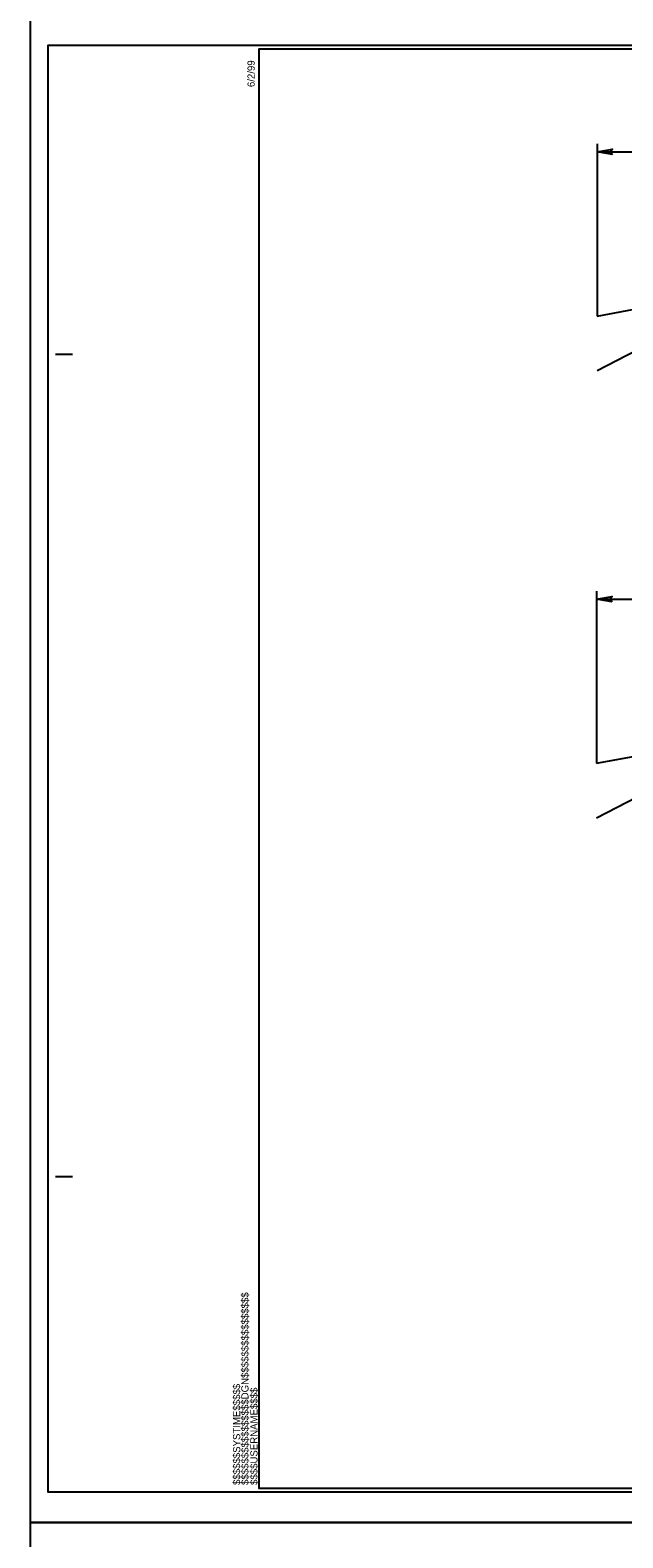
# Model space of a CAD drawing. Extents: x 981824 to 982276, y 44828 to 45204.
# Drawn here: x 982094.4 to 982129, y 45001.1 to 45089.1 of the extents above; entities that cross this region are included whole.
import ezdxf

# ---------------------------------------------------------------- set-up
doc = ezdxf.new("R2010")
doc.units = 0
for name, color, linetype in [('Old_Level_1', 7, 'Continuous'), ('Old_Level_18', 7, 'Continuous'), ('Old_Level_40', 7, 'Continuous'), ('Old_Level_41', 7, 'Continuous'), ('Old_Level_50', 7, 'Continuous'), ('Old_Level_51', 7, 'Continuous'), ('Old_Level_52', 7, 'Continuous'), ('Typical Terminator CELL', 7, 'Continuous')]:
    doc.layers.add(name, color=color, linetype=linetype)

msp = doc.modelspace()

# ---------------------------------------------------------------- linework, layer by layer
at = {"layer": 'Old_Level_1'}
for p, q in [((982127.455, 45082.429), (982127.455, 45072.384)), ((982127.455, 45081.961), (982136.994, 45081.961)), ((982127.455, 45069.205), (982136.994, 45074.163)), ((982127.455, 45072.384), (982136.994, 45074.163)), ((982127.423, 45056.322), (982127.423, 45046.278)), ((982127.423, 45055.854), (982136.961, 45055.854)), ((982127.423, 45043.098), (982136.961, 45048.056)), ((982127.423, 45046.278), (982136.961, 45048.056))]:
    msp.add_line(p, q, dxfattribs=at)
at = {"layer": 'Old_Level_18'}
msp.add_line((982107.72, 45003.969), (982107.72, 45003.969), dxfattribs=at)
msp.add_line((982107.72, 45003.969), (982107.72, 45003.969), dxfattribs=at)
msp.add_line((982107.72, 45003.969), (982107.72, 45003.969), dxfattribs=at)
msp.add_lwpolyline([(982227.72, 45087.969), (982107.72, 45087.969), (982107.72, 45003.969), (982227.72, 45003.969)], close=True, dxfattribs=at)
at = {"layer": 'Old_Level_40'}
msp.add_line((982107.72, 45003.969), (982107.72, 45003.969), dxfattribs=at)
msp.add_line((982107.72, 45003.969), (982107.72, 45003.969), dxfattribs=at)
msp.add_line((982107.72, 45003.969), (982107.72, 45003.969), dxfattribs=at)
msp.add_line((982107.72, 45003.969), (982107.72, 45003.969), dxfattribs=at)
msp.add_line((982107.72, 45003.969), (982107.72, 45003.969), dxfattribs=at)
msp.add_line((982107.72, 45003.969), (982107.72, 45003.969), dxfattribs=at)
at = {"layer": 'Old_Level_41'}
for p, q in [((982095.84, 45070.169), (982096.84, 45070.169)), ((982095.84, 45022.169), (982096.84, 45022.169))]:
    msp.add_line(p, q, dxfattribs=at)
msp.add_lwpolyline([(982110.72, 45003.969), (982110.72, 45003.969)], dxfattribs=at)
msp.add_lwpolyline([(982110.72, 45003.969), (982110.72, 45003.969)], dxfattribs=at)
at = {"layer": 'Old_Level_50'}
msp.add_line((982094.36, 45001.969), (982094.36, 45001.969), dxfattribs=at)
msp.add_lwpolyline([(982228.72, 45088.173), (982095.4, 45088.173), (982095.4, 45003.765), (982228.72, 45003.765)], close=True, dxfattribs=at)
at = {"layer": 'Old_Level_51'}
for points in [[(982229.08, 45089.969), (982094.36, 45089.969), (982094.36, 45001.969), (982229.08, 45001.969)], [(982229.08, 45001.969), (982094.36, 45001.969), (982094.36, 44913.969), (982229.08, 44913.969)]]:
    msp.add_lwpolyline(points, close=True, dxfattribs=at)
at = {"layer": 'Old_Level_52'}
msp.add_line((982095.4, 45003.765), (982095.4, 45003.765), dxfattribs=at)
at = {"layer": 'Typical Terminator CELL'}
for points in [[(982128.355, 45081.806), (982127.455, 45081.961), (982128.36, 45082.121), (982128.245, 45081.961)], [(982128.323, 45055.699), (982127.423, 45055.854), (982128.328, 45056.014), (982128.213, 45055.854)]]:
    msp.add_lwpolyline(points, close=True, dxfattribs=at)

# ---------------------------------------------------------------- texts
at = {"layer": 'Old_Level_41'}
for s, p in [('6/2/99', (982107.468, 45085.749)), ('$$$$$$$$$$$$$$$$DGN$$$$$$$$$$$$$$$$', (982107.108, 45004.158)), ('$$$$$$SYSTIME$$$$$', (982106.624, 45004.158)), ('$$$$USERNAME$$$$', (982107.634, 45004.159))]:
    msp.add_text(s, height=0.42, rotation=90, dxfattribs=at).set_placement(p)

doc.saveas('drawing.dxf')
